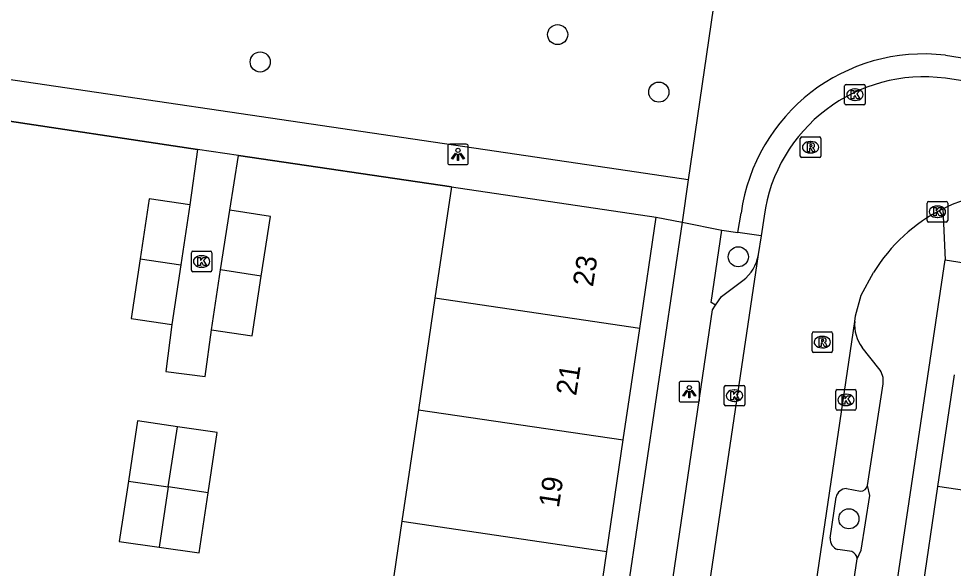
# Model space of a CAD drawing. Extents: x 164150 to 165261, y 382513 to 383432.
# Drawn here: x 164331.87 to 164377.35, y 383321.16 to 383347.93 of the extents above; entities that cross this region are included whole.
import ezdxf

# ---------------------------------------------------------------- set-up
doc = ezdxf.new("R2010")
doc.units = 0
for name, color, linetype in [('IMGEO_Boom', 7, 'Continuous'), ('IMGEO_Kolk', 7, 'Continuous'), ('IMGEO_Lichtpunt', 7, 'Continuous'), ('IMGEO_Muur', 7, 'Continuous'), ('IMGEO_Pand', 7, 'Continuous'), ('IMGEO_Pand_nummerreeks', 7, 'Continuous'), ('IMGEO_Parkeervlak_open', 7, 'Continuous'), ('IMGEO_Rijbaan_lokaal_open', 7, 'Continuous'), ('IMGEO_Rioolput', 7, 'Continuous'), ('IMGEO_Voetpad_open', 7, 'Continuous')]:
    doc.layers.add(name, color=color, linetype=linetype)

msp = doc.modelspace()

# ---------------------------------------------------------------- linework, layer by layer
at = {"layer": 'IMGEO_Boom'}
for centre in [(164358.098, 383347.155), (164343.625, 383345.823), (164363.023, 383344.356), (164366.889, 383336.334), (164372.272, 383323.573)]:
    msp.add_circle(centre, 0.489, dxfattribs=at)
at = {"layer": 'IMGEO_Kolk'}
for p, q in [((164372.065, 383343.802), (164372.065, 383344.654)), ((164372.14, 383344.728), (164372.992, 383344.728)), ((164372.553, 383344.508), (164372.578, 383344.508)), ((164373.066, 383344.654), (164373.066, 383343.802)), ((164372.576, 383343.948), (164372.551, 383343.948)), ((164372.992, 383343.728), (164372.14, 383343.728)), ((164376.077, 383338.101), (164376.077, 383338.953)), ((164376.152, 383339.027), (164377.004, 383339.027)), ((164377.078, 383338.953), (164377.078, 383338.101)), ((164376.565, 383338.807), (164376.59, 383338.807)), ((164377.004, 383338.027), (164376.152, 383338.027)), ((164376.588, 383338.247), (164376.563, 383338.247)), ((164340.349, 383336.606), (164341.201, 383336.606)), ((164340.274, 383335.68), (164340.274, 383336.532)), ((164340.762, 383336.386), (164340.787, 383336.386)), ((164341.275, 383336.532), (164341.275, 383335.68)), ((164340.785, 383335.826), (164340.76, 383335.826)), ((164341.201, 383335.606), (164340.349, 383335.606)), ((164366.204, 383329.146), (164366.204, 383329.998)), ((164366.279, 383330.072), (164367.131, 383330.072)), ((164366.692, 383329.852), (164366.717, 383329.852)), ((164367.205, 383329.998), (164367.205, 383329.146)), ((164371.63, 383328.938), (164371.63, 383329.79)), ((164371.705, 383329.864), (164372.557, 383329.864)), ((164372.631, 383329.79), (164372.631, 383328.938)), ((164372.118, 383329.644), (164372.143, 383329.644)), ((164367.131, 383329.072), (164366.279, 383329.072)), ((164366.715, 383329.292), (164366.69, 383329.292)), ((164372.557, 383328.864), (164371.705, 383328.864)), ((164372.141, 383329.084), (164372.116, 383329.084))]:
    msp.add_line(p, q, dxfattribs=at)
for points in [[(164372.065, 383343.802), (164372.065, 383344.654)], [(164372.14, 383344.728), (164372.992, 383344.728)], [(164372.386, 383344.428), (164372.509, 383344.428), (164372.509, 383344.277), (164372.639, 383344.428), (164372.803, 383344.428), (164372.657, 383344.277), (164372.81, 383344.028), (164372.658, 383344.028), (164372.573, 383344.192), (164372.509, 383344.125), (164372.509, 383344.028), (164372.386, 383344.028), (164372.386, 383344.428)], [(164373.066, 383344.654), (164373.066, 383343.802)], [(164372.992, 383343.728), (164372.14, 383343.728)], [(164376.077, 383338.101), (164376.077, 383338.953)], [(164376.152, 383339.027), (164377.004, 383339.027)], [(164377.078, 383338.953), (164377.078, 383338.101)], [(164376.398, 383338.727), (164376.521, 383338.727), (164376.521, 383338.576), (164376.651, 383338.727), (164376.815, 383338.727), (164376.669, 383338.576), (164376.822, 383338.327), (164376.67, 383338.327), (164376.585, 383338.491), (164376.521, 383338.424), (164376.521, 383338.327), (164376.398, 383338.327), (164376.398, 383338.727)], [(164377.004, 383338.027), (164376.152, 383338.027)], [(164340.349, 383336.606), (164341.201, 383336.606)], [(164340.274, 383335.68), (164340.274, 383336.532)], [(164340.595, 383336.306), (164340.718, 383336.306), (164340.718, 383336.155), (164340.848, 383336.306), (164341.012, 383336.306), (164340.866, 383336.155), (164341.019, 383335.906), (164340.867, 383335.906), (164340.782, 383336.07), (164340.718, 383336.003), (164340.718, 383335.906), (164340.595, 383335.906), (164340.595, 383336.306)], [(164341.275, 383336.532), (164341.275, 383335.68)], [(164341.201, 383335.606), (164340.349, 383335.606)], [(164366.204, 383329.146), (164366.204, 383329.998)], [(164366.279, 383330.072), (164367.131, 383330.072)], [(164366.525, 383329.772), (164366.648, 383329.772), (164366.648, 383329.621), (164366.778, 383329.772), (164366.942, 383329.772), (164366.796, 383329.621), (164366.949, 383329.372), (164366.797, 383329.372), (164366.712, 383329.536), (164366.648, 383329.469), (164366.648, 383329.372), (164366.525, 383329.372), (164366.525, 383329.772)], [(164367.205, 383329.998), (164367.205, 383329.146)], [(164371.63, 383328.938), (164371.63, 383329.79)], [(164371.705, 383329.864), (164372.557, 383329.864)], [(164372.631, 383329.79), (164372.631, 383328.938)], [(164371.951, 383329.564), (164372.074, 383329.564), (164372.074, 383329.413), (164372.204, 383329.564), (164372.368, 383329.564), (164372.222, 383329.413), (164372.375, 383329.164), (164372.223, 383329.164), (164372.138, 383329.328), (164372.074, 383329.261), (164372.074, 383329.164), (164371.951, 383329.164), (164371.951, 383329.564)], [(164367.131, 383329.072), (164366.279, 383329.072)], [(164372.557, 383328.864), (164371.705, 383328.864)]]:
    msp.add_lwpolyline(points, dxfattribs=at)
for centre, start, end in [((164372.142, 383344.652), 91.552, 178.448), ((164372.142, 383344.652), 91.552, 178.448), ((164372.99, 383344.652), 1.552, 88.448), ((164372.99, 383344.652), 1.552, 88.448), ((164372.142, 383343.804), 181.552, 268.448), ((164372.142, 383343.804), 181.552, 268.448), ((164372.99, 383343.804), 271.552, 358.448), ((164372.99, 383343.804), 271.552, 358.448), ((164376.154, 383338.951), 91.552, 178.448), ((164376.154, 383338.951), 91.552, 178.448), ((164377.002, 383338.951), 1.552, 88.448), ((164377.002, 383338.951), 1.552, 88.448), ((164376.154, 383338.103), 181.552, 268.448), ((164376.154, 383338.103), 181.552, 268.448), ((164377.002, 383338.103), 271.552, 358.448), ((164377.002, 383338.103), 271.552, 358.448), ((164340.351, 383336.53), 91.552, 178.448), ((164340.351, 383336.53), 91.552, 178.448), ((164341.199, 383336.53), 1.552, 88.448), ((164341.199, 383336.53), 1.552, 88.448), ((164340.351, 383335.682), 181.552, 268.448), ((164340.351, 383335.682), 181.552, 268.448), ((164341.199, 383335.682), 271.552, 358.448), ((164341.199, 383335.682), 271.552, 358.448), ((164366.281, 383329.996), 91.552, 178.448), ((164366.281, 383329.996), 91.552, 178.448), ((164367.129, 383329.996), 1.552, 88.448), ((164367.129, 383329.996), 1.552, 88.448), ((164371.707, 383329.788), 91.552, 178.448), ((164371.707, 383329.788), 91.552, 178.448), ((164372.555, 383329.788), 1.552, 88.448), ((164372.555, 383329.788), 1.552, 88.448), ((164366.281, 383329.148), 181.552, 268.448), ((164366.281, 383329.148), 181.552, 268.448), ((164367.129, 383329.148), 271.552, 358.448), ((164367.129, 383329.148), 271.552, 358.448), ((164371.707, 383328.94), 181.552, 268.448), ((164371.707, 383328.94), 181.552, 268.448), ((164372.555, 383328.94), 271.552, 358.448), ((164372.555, 383328.94), 271.552, 358.448)]:
    msp.add_arc(centre, 0.0765, start, end, dxfattribs=at)
for centre, major_axis, ratio, start_param, end_param in [((164372.552, 383344.228), (-0.387, 0.002), 0.722429, 4.712389, 7.853982), ((164372.577, 383344.228), (-0.39, 0.002), 0.717154, 1.570796, 4.712389), ((164376.564, 383338.527), (-0.387, 0.002), 0.722429, 4.712389, 7.853982), ((164376.589, 383338.527), (-0.39, 0.002), 0.717154, 1.570796, 4.712389), ((164340.761, 383336.106), (-0.387, 0.002), 0.722429, 4.712389, 7.853982), ((164340.786, 383336.106), (-0.39, 0.002), 0.717154, 1.570796, 4.712389), ((164366.691, 383329.572), (-0.387, 0.002), 0.722429, 4.712389, 7.853982), ((164366.716, 383329.572), (-0.39, 0.002), 0.717154, 1.570796, 4.712389), ((164372.117, 383329.364), (-0.387, 0.002), 0.722429, 4.712389, 7.853982), ((164372.142, 383329.364), (-0.39, 0.002), 0.717154, 1.570796, 4.712389)]:
    msp.add_ellipse(centre, major_axis=major_axis, ratio=ratio, start_param=start_param, end_param=end_param, dxfattribs=at)
at = {"layer": 'IMGEO_Lichtpunt'}
for p, q in [((164352.752, 383341.723), (164352.752, 383340.916)), ((164352.752, 383341.723), (164352.752, 383340.916)), ((164353.654, 383341.818), (164352.846, 383341.818)), ((164353.654, 383341.818), (164352.846, 383341.818)), ((164353.748, 383340.916), (164353.748, 383341.723)), ((164353.748, 383340.916), (164353.748, 383341.723)), ((164352.846, 383340.822), (164353.654, 383340.822)), ((164352.846, 383340.822), (164353.654, 383340.822)), ((164364.909, 383330.263), (164364.101, 383330.263)), ((164364.909, 383330.263), (164364.101, 383330.263)), ((164364.007, 383330.168), (164364.007, 383329.361)), ((164364.007, 383330.168), (164364.007, 383329.361)), ((164365.003, 383329.361), (164365.003, 383330.168)), ((164365.003, 383329.361), (164365.003, 383330.168)), ((164364.101, 383329.267), (164364.909, 383329.267)), ((164364.101, 383329.267), (164364.909, 383329.267))]:
    msp.add_line(p, q, dxfattribs=at)
for points in [[(164353.126, 383341.387), (164353.165, 383341.359), (164352.977, 383341.097), (164352.939, 383341.124), (164353.126, 383341.387)], [(164353.228, 383341.339), (164353.275, 383341.339), (164353.275, 383341.017), (164353.228, 383341.017), (164353.228, 383341.339)], [(164353.338, 383341.359), (164353.376, 383341.386), (164353.563, 383341.124), (164353.524, 383341.096), (164353.338, 383341.359)], [(164364.381, 383329.832), (164364.42, 383329.804), (164364.232, 383329.542), (164364.194, 383329.569), (164364.381, 383329.832)], [(164364.483, 383329.784), (164364.53, 383329.784), (164364.53, 383329.462), (164364.483, 383329.462), (164364.483, 383329.784)], [(164364.593, 383329.804), (164364.631, 383329.831), (164364.818, 383329.569), (164364.779, 383329.541), (164364.593, 383329.804)]]:
    msp.add_lwpolyline(points, dxfattribs=at)
for centre in [(164353.251, 383341.521), (164364.506, 383329.966)]:
    msp.add_circle(centre, 0.0994, dxfattribs=at)
for centre, start, end in [((164352.846, 383341.723), 90, 180), ((164352.846, 383341.723), 90, 180), ((164353.654, 383341.723), 0, 90), ((164353.654, 383341.723), 0, 90), ((164352.846, 383340.916), 180, 270), ((164352.846, 383340.916), 180, 270), ((164353.654, 383340.916), 270, 0), ((164353.654, 383340.916), 270, 360), ((164364.101, 383330.168), 90, 180), ((164364.101, 383330.168), 90, 180), ((164364.909, 383330.168), 0, 90), ((164364.909, 383330.168), 0, 90), ((164364.101, 383329.361), 180, 270), ((164364.101, 383329.361), 180, 270), ((164364.909, 383329.361), 270, 0), ((164364.909, 383329.361), 270, 360)]:
    msp.add_arc(centre, 0.0946, start, end, dxfattribs=at)
at = {"layer": 'IMGEO_Muur'}
for points in [[(164340.573, 383341.556), (164330.233, 383343.112)], [(164352.927, 383339.746), (164342.573, 383341.273)]]:
    msp.add_lwpolyline(points, dxfattribs=at)
at = {"layer": 'IMGEO_Pand'}
for points in [[(164352.927, 383339.746), (164352.125, 383334.32)], [(164352.927, 383339.746), (164362.9, 383338.272)], [(164340.197, 383338.863), (164338.219, 383339.157), (164337.785, 383336.242)], [(164340.197, 383338.863), (164339.764, 383335.948)], [(164341.696, 383335.692), (164342.142, 383338.599)], [(164343.673, 383335.389), (164344.119, 383338.296), (164342.142, 383338.599)], [(164362.098, 383332.846), (164362.9, 383338.272)], [(164337.785, 383336.242), (164337.352, 383333.327), (164339.33, 383333.033)], [(164337.785, 383336.242), (164339.764, 383335.948)], [(164339.764, 383335.948), (164339.33, 383333.033)], [(164341.25, 383332.785), (164341.696, 383335.692)], [(164343.673, 383335.389), (164341.696, 383335.692)], [(164341.25, 383332.785), (164343.227, 383332.482), (164343.673, 383335.389)], [(164352.125, 383334.32), (164351.322, 383328.888)], [(164362.098, 383332.846), (164352.125, 383334.32)], [(164361.295, 383327.414), (164362.098, 383332.846)], [(164377.394, 383330.586), (164376.589, 383325.154)], [(164351.322, 383328.888), (164350.519, 383323.456)], [(164351.322, 383328.888), (164361.295, 383327.414)], [(164339.598, 383328.056), (164337.661, 383328.338), (164337.212, 383325.407)], [(164339.153, 383325.125), (164339.598, 383328.056)], [(164341.094, 383324.842), (164341.534, 383327.774), (164339.598, 383328.056)], [(164360.493, 383321.982), (164361.295, 383327.414)], [(164337.212, 383325.407), (164336.764, 383322.476), (164338.708, 383322.194)], [(164337.212, 383325.407), (164339.153, 383325.125)], [(164339.153, 383325.125), (164338.708, 383322.194)], [(164338.708, 383322.194), (164340.653, 383321.911), (164341.094, 383324.842)], [(164341.094, 383324.842), (164339.153, 383325.125)], [(164376.589, 383325.154), (164375.783, 383319.723)], [(164386.561, 383323.676), (164376.589, 383325.154)], [(164350.519, 383323.456), (164349.717, 383318.024)], [(164350.519, 383323.456), (164360.493, 383321.982)], [(164359.69, 383316.55), (164360.493, 383321.982)]]:
    msp.add_lwpolyline(points, dxfattribs=at)
at = {"layer": 'IMGEO_Parkeervlak_open'}
for points in [[(164365.787, 383333.983), (164366.068, 383334.399), (164367.115, 383335.176)], [(164372.15, 383325.044), (164372.835, 383324.923)], [(164371.357, 383322.635), (164371.645, 383324.631)], [(164372.417, 383321.974), (164371.727, 383322.073)]]:
    msp.add_lwpolyline(points, dxfattribs=at)
for centre, radius, start, end in [((164365.907, 383336.746), 1.981, 307.586, 351.1152), ((164372.152, 383324.527), 0.517, 90.1825, 168.3716), ((164372.844, 383325.272), 0.349, 268.4622, 346.3729), ((164371.892, 383322.584), 0.537, 174.573, 252.1458), ((164372.258, 383321.586), 0.419, 5.1458, 67.6452)]:
    msp.add_arc(centre, radius, start, end, dxfattribs=at)
at = {"layer": 'IMGEO_Rijbaan_lokaal_open'}
for points in [[(164379.283, 383344.677), (164376.965, 383345.026)], [(164368.14, 383338.316), (164368.004, 383337.357)], [(164368.004, 383337.357), (164367.864, 383336.44)], [(164367.864, 383336.44), (164363.859, 383309.529)], [(164372.554, 383333.188), (164372.593, 383333.453), (164372.872, 383334.46), (164373.469, 383335.569)], [(164368.961, 383308.759), (164372.554, 383333.188)]]:
    msp.add_lwpolyline(points, dxfattribs=at)
for centre, radius, start, end in [((164375.912, 383337.253), 7.844, 82.284, 172.2104), ((164380.473, 383331.318), 8.196, 83.7281, 116.2315), ((164380.476, 383331.323), 8.192, 116.2664, 148.7868)]:
    msp.add_arc(centre, radius, start, end, dxfattribs=at)
at = {"layer": 'IMGEO_Rioolput'}
for p, q in [((164369.906, 383341.243), (164369.906, 383342.095)), ((164369.981, 383342.169), (164370.833, 383342.169)), ((164370.907, 383342.095), (164370.907, 383341.243)), ((164370.394, 383341.949), (164370.419, 383341.949)), ((164370.833, 383341.169), (164369.981, 383341.169)), ((164370.417, 383341.389), (164370.392, 383341.389)), ((164370.476, 383331.753), (164370.476, 383332.605)), ((164370.551, 383332.679), (164371.403, 383332.679)), ((164371.477, 383332.605), (164371.477, 383331.753)), ((164370.964, 383332.459), (164370.989, 383332.459)), ((164371.403, 383331.679), (164370.551, 383331.679)), ((164370.987, 383331.899), (164370.962, 383331.899))]:
    msp.add_line(p, q, dxfattribs=at)
for points in [[(164369.906, 383341.243), (164369.906, 383342.095)], [(164369.981, 383342.169), (164370.833, 383342.169)], [(164370.907, 383342.095), (164370.907, 383341.243)], [(164370.495, 383341.867), (164370.243, 383341.869), (164370.243, 383341.469)], [(164370.243, 383341.469), (164370.367, 383341.469), (164370.367, 383341.631), (164370.378, 383341.631)], [(164370.421, 383341.788), (164370.367, 383341.788), (164370.367, 383341.707)], [(164370.367, 383341.707), (164370.419, 383341.707)], [(164370.425, 383341.602), (164370.496, 383341.469), (164370.636, 383341.469), (164370.571, 383341.595)], [(164370.833, 383341.169), (164369.981, 383341.169)], [(164370.476, 383331.753), (164370.476, 383332.605)], [(164370.551, 383332.679), (164371.403, 383332.679)], [(164371.477, 383332.605), (164371.477, 383331.753)], [(164371.065, 383332.377), (164370.813, 383332.379), (164370.813, 383331.979)], [(164370.813, 383331.979), (164370.937, 383331.979), (164370.937, 383332.141), (164370.948, 383332.141)], [(164370.991, 383332.298), (164370.937, 383332.298), (164370.937, 383332.217)], [(164370.937, 383332.217), (164370.989, 383332.217)], [(164370.995, 383332.112), (164371.066, 383331.979), (164371.206, 383331.979), (164371.141, 383332.105)], [(164371.403, 383331.679), (164370.551, 383331.679)]]:
    msp.add_lwpolyline(points, dxfattribs=at)
for centre, radius, start, end in [((164369.983, 383342.093), 0.0765, 91.552, 178.448), ((164369.983, 383342.093), 0.0765, 91.552, 178.448), ((164370.831, 383342.093), 0.0765, 1.552, 88.448), ((164370.831, 383342.093), 0.0765, 1.552, 88.448), ((164370.377, 383341.578), 0.0533, 26.0293, 88.6989), ((164370.403, 383341.896), 0.19, 274.7715, 282.9687), ((164370.427, 383341.692), 0.0964, 77.0061, 93.1865), ((164370.441, 383341.749), 0.0378, 276.6634, 79.6772), ((164370.494, 383341.757), 0.109, 350.3612, 89.416), ((164370.492, 383341.757), 0.112, 277.5842, 350.9817), ((164370.476, 383341.542), 0.108, 29.5134, 73.7905), ((164369.983, 383341.245), 0.0765, 181.552, 268.448), ((164369.983, 383341.245), 0.0765, 181.552, 268.448), ((164370.831, 383341.245), 0.0765, 271.552, 358.448), ((164370.831, 383341.245), 0.0765, 271.552, 358.448), ((164370.553, 383332.603), 0.0765, 91.552, 178.448), ((164370.553, 383332.603), 0.0765, 91.552, 178.448), ((164371.401, 383332.603), 0.0765, 1.552, 88.448), ((164371.401, 383332.603), 0.0765, 1.552, 88.448), ((164370.947, 383332.088), 0.0533, 26.0293, 88.6989), ((164370.973, 383332.406), 0.19, 274.7715, 282.9687), ((164370.997, 383332.202), 0.0964, 77.0061, 93.1865), ((164371.011, 383332.259), 0.0378, 276.6634, 79.6772), ((164371.064, 383332.267), 0.109, 350.3612, 89.416), ((164371.062, 383332.267), 0.112, 277.5842, 350.9817), ((164371.046, 383332.052), 0.108, 29.5134, 73.7905), ((164370.553, 383331.755), 0.0765, 181.552, 268.448), ((164370.553, 383331.755), 0.0765, 181.552, 268.448), ((164371.401, 383331.755), 0.0765, 271.552, 358.448), ((164371.401, 383331.755), 0.0765, 271.552, 358.448)]:
    msp.add_arc(centre, radius, start, end, dxfattribs=at)
for centre, major_axis, ratio, start_param, end_param in [((164370.393, 383341.669), (-0.387, 0.002), 0.722429, 4.712389, 7.853982), ((164370.418, 383341.669), (-0.39, 0.002), 0.717154, 1.570796, 4.712389), ((164370.963, 383332.179), (-0.387, 0.002), 0.722429, 4.712389, 7.853982), ((164370.988, 383332.179), (-0.39, 0.002), 0.717154, 1.570796, 4.712389)]:
    msp.add_ellipse(centre, major_axis=major_axis, ratio=ratio, start_param=start_param, end_param=end_param, dxfattribs=at)
at = {"layer": 'IMGEO_Voetpad_open'}
for points in [[(164366.226, 383351.016), (164366.01, 383350.778), (164364.451, 383340.089)], [(164364.451, 383340.089), (164361.497, 383340.519), (164319.267, 383346.752), (164317.302, 383347.003), (164312.229, 383312.499)], [(164376.967, 383346.15), (164379.423, 383345.762), (164379.283, 383344.677)], [(164330.233, 383343.112), (164340.573, 383341.556)], [(164340.573, 383341.556), (164340.197, 383338.863)], [(164342.573, 383341.273), (164340.573, 383341.556)], [(164342.142, 383338.599), (164342.573, 383341.273)], [(164342.573, 383341.273), (164352.927, 383339.746)], [(164364.451, 383340.089), (164364.159, 383338.027)], [(164366.863, 383337.519), (164367.025, 383338.456)], [(164376.85, 383338.67), (164376.956, 383336.181)], [(164364.159, 383338.027), (164359.341, 383305.521), (164358.085, 383305.692)], [(164362.9, 383338.272), (164364.159, 383338.027)], [(164364.159, 383338.027), (164366.096, 383337.628)], [(164365.787, 383333.983), (164365.568, 383334.108), (164366.096, 383337.628)], [(164366.096, 383337.628), (164366.863, 383337.519)], [(164368.004, 383337.357), (164366.863, 383337.519)], [(164373.371, 383303.448), (164372.113, 383303.598), (164376.956, 383336.181)], [(164376.956, 383336.181), (164378.196, 383335.997)], [(164362.433, 383312.01), (164365.628, 383333.748), (164365.787, 383333.983)], [(164339.33, 383333.033), (164339.035, 383330.752), (164340.955, 383330.504), (164341.25, 383332.785)], [(164373.725, 383330.891), (164372.911, 383331.914)], [(164373.184, 383325.19), (164373.932, 383330.155)], [(164372.675, 383321.624), (164372.866, 383322.052), (164373.283, 383324.707), (164373.184, 383325.19)], [(164371.045, 383310.733), (164372.675, 383321.624)]]:
    msp.add_lwpolyline(points, dxfattribs=at)
for centre, radius, start, end in [((164375.913, 383337.242), 8.971, 83.2525, 172.2192), ((164374.478, 383333.04), 1.929, 175.601, 215.7068), ((164373.029, 383330.298), 0.915, 351.0026, 40.4147)]:
    msp.add_arc(centre, radius, start, end, dxfattribs=at)

# ---------------------------------------------------------------- texts
at = {"layer": 'IMGEO_Pand_nummerreeks'}
for s, p in [('23', (164359.814, 383334.842)), ('21', (164358.996, 383329.537)), ('19', (164358.154, 383324.077))]:
    msp.add_text(s, height=1, rotation=81.2314, dxfattribs=at).set_placement(p)

doc.saveas('drawing.dxf')
